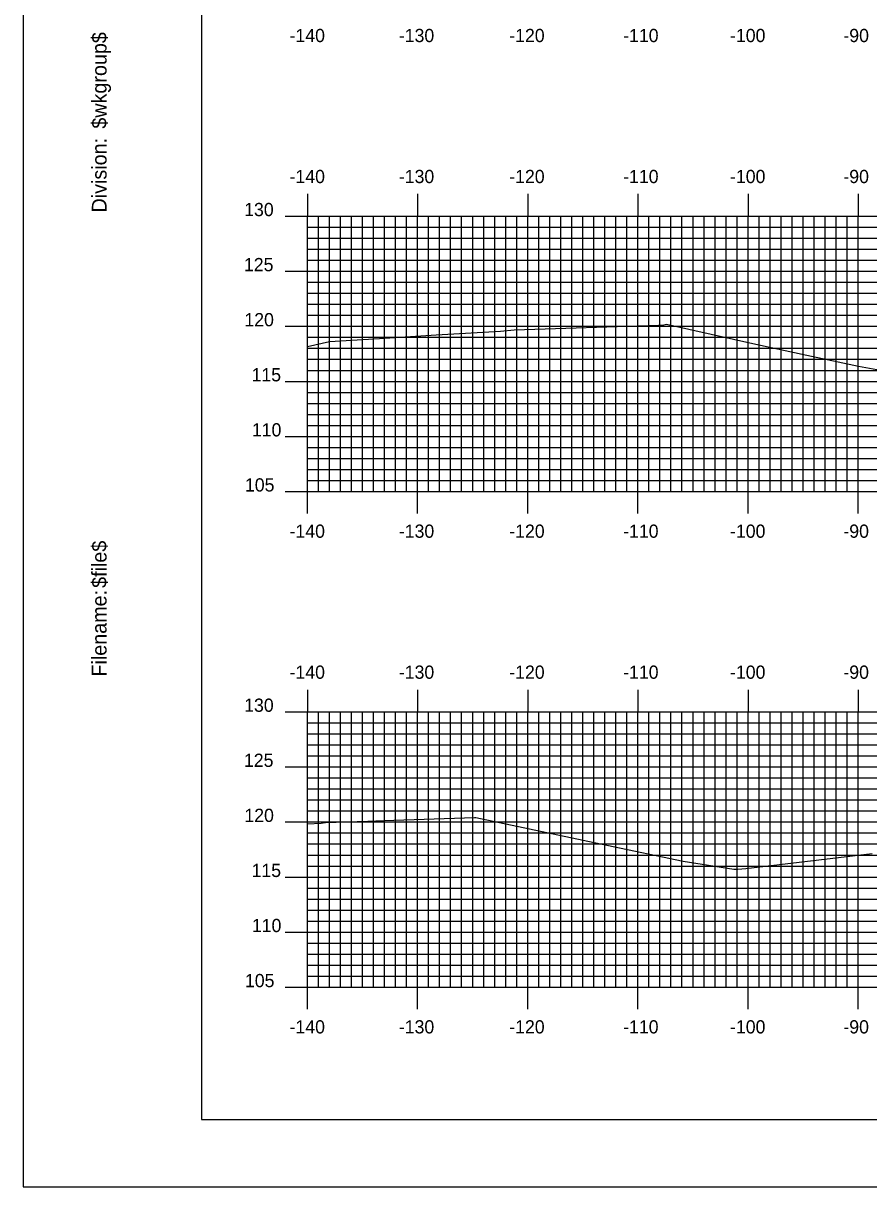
# Model space of a CAD drawing. Extents: x 1685979 to 1686323, y 461260 to 461480.
# Drawn here: x 1685979.5 to 1686056.2, y 461260 to 461365.6 of the extents above; entities that cross this region are included whole.
import ezdxf

# ---------------------------------------------------------------- set-up
doc = ezdxf.new("R2010")
doc.units = 0
for name, color, linetype in [('BORDER', 7, 'Continuous'), ('H_V ANNOTATION', 7, 'Continuous'), ('M_Roadway_Centerline', 7, 'Continuous'), ('MAJOR', 7, 'Continuous'), ('MINOR', 7, 'Continuous'), ('PLOT BOUNDARY', 7, 'Continuous'), ('S_Roadway_Centerline', 7, 'Continuous')]:
    doc.layers.add(name, color=color, linetype=linetype)

msp = doc.modelspace()

# ---------------------------------------------------------------- linework, layer by layer
at = {"layer": 'BORDER'}
msp.add_lwpolyline([(1685995.66, 461266.07), (1686315.66, 461266.07), (1686315.66, 461476.07), (1685995.66, 461476.07)], close=True, dxfattribs=at)
at = {"layer": 'MAJOR'}
for p, q in [((1686005.26, 461350.08), (1686005.26, 461348.07)), ((1686015.26, 461350.08), (1686015.26, 461348.07)), ((1686025.26, 461350.08), (1686025.26, 461348.07)), ((1686035.26, 461350.08), (1686035.26, 461348.07)), ((1686045.26, 461350.08), (1686045.26, 461348.07)), ((1686055.26, 461350.08), (1686055.26, 461348.07)), ((1686003.25, 461348.07), (1686005.26, 461348.07)), ((1686005.26, 461348.07), (1686285.26, 461348.07)), ((1686005.26, 461323.07), (1686005.26, 461348.07)), ((1686005.26, 461323.07), (1686005.26, 461348.07)), ((1686005.26, 461348.07), (1686285.26, 461348.07)), ((1686015.26, 461323.07), (1686015.26, 461348.07)), ((1686025.26, 461323.07), (1686025.26, 461348.07)), ((1686035.26, 461323.07), (1686035.26, 461348.07)), ((1686045.26, 461323.07), (1686045.26, 461348.07)), ((1686055.26, 461323.07), (1686055.26, 461348.07)), ((1686003.25, 461343.07), (1686005.26, 461343.07)), ((1686005.26, 461343.07), (1686285.26, 461343.07)), ((1686003.25, 461338.07), (1686005.26, 461338.07)), ((1686005.26, 461338.07), (1686285.26, 461338.07)), ((1686003.25, 461333.07), (1686005.26, 461333.07)), ((1686005.26, 461333.07), (1686285.26, 461333.07)), ((1686003.25, 461328.07), (1686005.26, 461328.07)), ((1686005.26, 461328.07), (1686285.26, 461328.07)), ((1686003.25, 461323.07), (1686005.26, 461323.07)), ((1686005.26, 461323.07), (1686285.26, 461323.07)), ((1686005.26, 461323.07), (1686285.26, 461323.07)), ((1686005.26, 461321.07), (1686005.26, 461323.07)), ((1686015.26, 461321.07), (1686015.26, 461323.07)), ((1686025.26, 461321.07), (1686025.26, 461323.07)), ((1686035.26, 461321.07), (1686035.26, 461323.07)), ((1686045.26, 461321.07), (1686045.26, 461323.07)), ((1686055.26, 461321.07), (1686055.26, 461323.07)), ((1686005.26, 461305.08), (1686005.26, 461303.07)), ((1686015.26, 461305.08), (1686015.26, 461303.07)), ((1686025.26, 461305.08), (1686025.26, 461303.07)), ((1686035.26, 461305.08), (1686035.26, 461303.07)), ((1686045.26, 461305.08), (1686045.26, 461303.07)), ((1686055.26, 461305.08), (1686055.26, 461303.07)), ((1686003.25, 461303.07), (1686005.26, 461303.07)), ((1686005.26, 461303.07), (1686285.26, 461303.07)), ((1686005.26, 461278.07), (1686005.26, 461303.07)), ((1686005.26, 461278.07), (1686005.26, 461303.07)), ((1686005.26, 461303.07), (1686285.26, 461303.07)), ((1686015.26, 461278.07), (1686015.26, 461303.07)), ((1686025.26, 461278.07), (1686025.26, 461303.07)), ((1686035.26, 461278.07), (1686035.26, 461303.07)), ((1686045.26, 461278.07), (1686045.26, 461303.07)), ((1686055.26, 461278.07), (1686055.26, 461303.07)), ((1686003.25, 461298.07), (1686005.26, 461298.07)), ((1686005.26, 461298.07), (1686285.26, 461298.07)), ((1686003.25, 461293.07), (1686005.26, 461293.07)), ((1686005.26, 461293.07), (1686285.26, 461293.07)), ((1686003.25, 461288.07), (1686005.26, 461288.07)), ((1686005.26, 461288.07), (1686285.26, 461288.07)), ((1686003.25, 461283.07), (1686005.26, 461283.07)), ((1686005.26, 461283.07), (1686285.26, 461283.07)), ((1686003.25, 461278.07), (1686005.26, 461278.07)), ((1686005.26, 461278.07), (1686285.26, 461278.07)), ((1686005.26, 461278.07), (1686285.26, 461278.07)), ((1686005.26, 461276.07), (1686005.26, 461278.07)), ((1686015.26, 461276.07), (1686015.26, 461278.07)), ((1686025.26, 461276.07), (1686025.26, 461278.07)), ((1686035.26, 461276.07), (1686035.26, 461278.07)), ((1686045.26, 461276.07), (1686045.26, 461278.07)), ((1686055.26, 461276.07), (1686055.26, 461278.07))]:
    msp.add_line(p, q, dxfattribs=at)
at = {"layer": 'MINOR'}
for p, q in [((1686006.26, 461323.07), (1686006.26, 461348.07)), ((1686007.26, 461323.07), (1686007.26, 461348.07)), ((1686008.26, 461323.07), (1686008.26, 461348.07)), ((1686009.26, 461323.07), (1686009.26, 461348.07)), ((1686010.26, 461323.07), (1686010.26, 461348.07)), ((1686011.26, 461323.07), (1686011.26, 461348.07)), ((1686012.26, 461323.07), (1686012.26, 461348.07)), ((1686013.26, 461323.07), (1686013.26, 461348.07)), ((1686014.26, 461323.07), (1686014.26, 461348.07)), ((1686016.26, 461323.07), (1686016.26, 461348.07)), ((1686017.26, 461323.07), (1686017.26, 461348.07)), ((1686018.26, 461323.07), (1686018.26, 461348.07)), ((1686019.26, 461323.07), (1686019.26, 461348.07)), ((1686020.26, 461323.07), (1686020.26, 461348.07)), ((1686021.26, 461323.07), (1686021.26, 461348.07)), ((1686022.26, 461323.07), (1686022.26, 461348.07)), ((1686023.26, 461323.07), (1686023.26, 461348.07)), ((1686024.26, 461323.07), (1686024.26, 461348.07)), ((1686026.26, 461323.07), (1686026.26, 461348.07)), ((1686027.26, 461323.07), (1686027.26, 461348.07)), ((1686028.26, 461323.07), (1686028.26, 461348.07)), ((1686029.26, 461323.07), (1686029.26, 461348.07)), ((1686030.26, 461323.07), (1686030.26, 461348.07)), ((1686031.26, 461323.07), (1686031.26, 461348.07)), ((1686032.26, 461323.07), (1686032.26, 461348.07)), ((1686033.26, 461323.07), (1686033.26, 461348.07)), ((1686034.26, 461323.07), (1686034.26, 461348.07)), ((1686036.26, 461323.07), (1686036.26, 461348.07)), ((1686037.26, 461323.07), (1686037.26, 461348.07)), ((1686038.26, 461323.07), (1686038.26, 461348.07)), ((1686039.26, 461323.07), (1686039.26, 461348.07)), ((1686040.26, 461323.07), (1686040.26, 461348.07)), ((1686041.26, 461323.07), (1686041.26, 461348.07)), ((1686042.26, 461323.07), (1686042.26, 461348.07)), ((1686043.26, 461323.07), (1686043.26, 461348.07)), ((1686044.26, 461323.07), (1686044.26, 461348.07)), ((1686046.26, 461323.07), (1686046.26, 461348.07)), ((1686047.26, 461323.07), (1686047.26, 461348.07)), ((1686048.26, 461323.07), (1686048.26, 461348.07)), ((1686049.26, 461323.07), (1686049.26, 461348.07)), ((1686050.26, 461323.07), (1686050.26, 461348.07)), ((1686051.26, 461323.07), (1686051.26, 461348.07)), ((1686052.26, 461323.07), (1686052.26, 461348.07)), ((1686053.26, 461323.07), (1686053.26, 461348.07)), ((1686054.26, 461323.07), (1686054.26, 461348.07)), ((1686005.26, 461347.07), (1686285.26, 461347.07)), ((1686005.26, 461347.07), (1686007.26, 461347.07)), ((1686005.26, 461346.07), (1686285.26, 461346.07)), ((1686005.26, 461346.07), (1686007.26, 461346.07)), ((1686005.26, 461345.07), (1686285.26, 461345.07)), ((1686005.26, 461345.07), (1686007.26, 461345.07)), ((1686005.26, 461344.07), (1686285.26, 461344.07)), ((1686005.26, 461344.07), (1686007.26, 461344.07)), ((1686005.26, 461342.07), (1686285.26, 461342.07)), ((1686005.26, 461342.07), (1686007.26, 461342.07)), ((1686005.26, 461341.07), (1686285.26, 461341.07)), ((1686005.26, 461341.07), (1686007.26, 461341.07)), ((1686005.26, 461340.07), (1686285.26, 461340.07)), ((1686005.26, 461340.07), (1686007.26, 461340.07)), ((1686005.26, 461339.07), (1686285.26, 461339.07)), ((1686005.26, 461339.07), (1686007.26, 461339.07)), ((1686005.26, 461337.07), (1686285.26, 461337.07)), ((1686005.26, 461337.07), (1686007.26, 461337.07)), ((1686005.26, 461336.07), (1686285.26, 461336.07)), ((1686005.26, 461336.07), (1686007.26, 461336.07)), ((1686005.26, 461335.07), (1686285.26, 461335.07)), ((1686005.26, 461335.07), (1686007.26, 461335.07)), ((1686005.26, 461334.07), (1686285.26, 461334.07)), ((1686005.26, 461334.07), (1686007.26, 461334.07)), ((1686005.26, 461332.07), (1686285.26, 461332.07)), ((1686005.26, 461332.07), (1686007.26, 461332.07)), ((1686005.26, 461331.07), (1686285.26, 461331.07)), ((1686005.26, 461331.07), (1686007.26, 461331.07)), ((1686005.26, 461330.07), (1686285.26, 461330.07)), ((1686005.26, 461330.07), (1686007.26, 461330.07)), ((1686005.26, 461329.07), (1686285.26, 461329.07)), ((1686005.26, 461329.07), (1686007.26, 461329.07)), ((1686005.26, 461327.07), (1686285.26, 461327.07)), ((1686005.26, 461327.07), (1686007.26, 461327.07)), ((1686005.26, 461326.07), (1686285.26, 461326.07)), ((1686005.26, 461326.07), (1686007.26, 461326.07)), ((1686005.26, 461325.07), (1686285.26, 461325.07)), ((1686005.26, 461325.07), (1686007.26, 461325.07)), ((1686005.26, 461324.07), (1686285.26, 461324.07)), ((1686005.26, 461324.07), (1686007.26, 461324.07)), ((1686006.26, 461278.07), (1686006.26, 461303.07)), ((1686007.26, 461278.07), (1686007.26, 461303.07)), ((1686008.26, 461278.07), (1686008.26, 461303.07)), ((1686009.26, 461278.07), (1686009.26, 461303.07)), ((1686010.26, 461278.07), (1686010.26, 461303.07)), ((1686011.26, 461278.07), (1686011.26, 461303.07)), ((1686012.26, 461278.07), (1686012.26, 461303.07)), ((1686013.26, 461278.07), (1686013.26, 461303.07)), ((1686014.26, 461278.07), (1686014.26, 461303.07)), ((1686016.26, 461278.07), (1686016.26, 461303.07)), ((1686017.26, 461278.07), (1686017.26, 461303.07)), ((1686018.26, 461278.07), (1686018.26, 461303.07)), ((1686019.26, 461278.07), (1686019.26, 461303.07)), ((1686020.26, 461278.07), (1686020.26, 461303.07)), ((1686021.26, 461278.07), (1686021.26, 461303.07)), ((1686022.26, 461278.07), (1686022.26, 461303.07)), ((1686023.26, 461278.07), (1686023.26, 461303.07)), ((1686024.26, 461278.07), (1686024.26, 461303.07)), ((1686026.26, 461278.07), (1686026.26, 461303.07)), ((1686027.26, 461278.07), (1686027.26, 461303.07)), ((1686028.26, 461278.07), (1686028.26, 461303.07)), ((1686029.26, 461278.07), (1686029.26, 461303.07)), ((1686030.26, 461278.07), (1686030.26, 461303.07)), ((1686031.26, 461278.07), (1686031.26, 461303.07)), ((1686032.26, 461278.07), (1686032.26, 461303.07)), ((1686033.26, 461278.07), (1686033.26, 461303.07)), ((1686034.26, 461278.07), (1686034.26, 461303.07)), ((1686036.26, 461278.07), (1686036.26, 461303.07)), ((1686037.26, 461278.07), (1686037.26, 461303.07)), ((1686038.26, 461278.07), (1686038.26, 461303.07)), ((1686039.26, 461278.07), (1686039.26, 461303.07)), ((1686040.26, 461278.07), (1686040.26, 461303.07)), ((1686041.26, 461278.07), (1686041.26, 461303.07)), ((1686042.26, 461278.07), (1686042.26, 461303.07)), ((1686043.26, 461278.07), (1686043.26, 461303.07)), ((1686044.26, 461278.07), (1686044.26, 461303.07)), ((1686046.26, 461278.07), (1686046.26, 461303.07)), ((1686047.26, 461278.07), (1686047.26, 461303.07)), ((1686048.26, 461278.07), (1686048.26, 461303.07)), ((1686049.26, 461278.07), (1686049.26, 461303.07)), ((1686050.26, 461278.07), (1686050.26, 461303.07)), ((1686051.26, 461278.07), (1686051.26, 461303.07)), ((1686052.26, 461278.07), (1686052.26, 461303.07)), ((1686053.26, 461278.07), (1686053.26, 461303.07)), ((1686054.26, 461278.07), (1686054.26, 461303.07)), ((1686005.26, 461302.07), (1686285.26, 461302.07)), ((1686005.26, 461302.07), (1686007.26, 461302.07)), ((1686005.26, 461301.07), (1686285.26, 461301.07)), ((1686005.26, 461301.07), (1686007.26, 461301.07)), ((1686005.26, 461300.07), (1686285.26, 461300.07)), ((1686005.26, 461300.07), (1686007.26, 461300.07)), ((1686005.26, 461299.07), (1686285.26, 461299.07)), ((1686005.26, 461299.07), (1686007.26, 461299.07)), ((1686005.26, 461297.07), (1686285.26, 461297.07)), ((1686005.26, 461297.07), (1686007.26, 461297.07)), ((1686005.26, 461296.07), (1686285.26, 461296.07)), ((1686005.26, 461296.07), (1686007.26, 461296.07)), ((1686005.26, 461295.07), (1686285.26, 461295.07)), ((1686005.26, 461295.07), (1686007.26, 461295.07)), ((1686005.26, 461294.07), (1686285.26, 461294.07)), ((1686005.26, 461294.07), (1686007.26, 461294.07)), ((1686005.26, 461292.07), (1686285.26, 461292.07)), ((1686005.26, 461292.07), (1686007.26, 461292.07)), ((1686005.26, 461291.07), (1686285.26, 461291.07)), ((1686005.26, 461291.07), (1686007.26, 461291.07)), ((1686005.26, 461290.07), (1686285.26, 461290.07)), ((1686005.26, 461290.07), (1686007.26, 461290.07)), ((1686005.26, 461289.07), (1686285.26, 461289.07)), ((1686005.26, 461289.07), (1686007.26, 461289.07)), ((1686005.26, 461287.07), (1686285.26, 461287.07)), ((1686005.26, 461287.07), (1686007.26, 461287.07)), ((1686005.26, 461286.07), (1686285.26, 461286.07)), ((1686005.26, 461286.07), (1686007.26, 461286.07)), ((1686005.26, 461285.07), (1686285.26, 461285.07)), ((1686005.26, 461285.07), (1686007.26, 461285.07)), ((1686005.26, 461284.07), (1686285.26, 461284.07)), ((1686005.26, 461284.07), (1686007.26, 461284.07)), ((1686005.26, 461282.07), (1686285.26, 461282.07)), ((1686005.26, 461282.07), (1686007.26, 461282.07)), ((1686005.26, 461281.07), (1686285.26, 461281.07)), ((1686005.26, 461281.07), (1686007.26, 461281.07)), ((1686005.26, 461280.07), (1686285.26, 461280.07)), ((1686005.26, 461280.07), (1686007.26, 461280.07)), ((1686005.26, 461279.07), (1686285.26, 461279.07)), ((1686005.26, 461279.07), (1686007.26, 461279.07))]:
    msp.add_line(p, q, dxfattribs=at)
at = {"layer": 'PLOT BOUNDARY'}
msp.add_lwpolyline([(1685979.47, 461259.95), (1686319.47, 461259.95), (1686319.47, 461479.95), (1685979.47, 461479.95)], close=True, dxfattribs=at)
at = {"layer": 'S_Roadway_Centerline'}
for points in [[(1686005.26, 461336.24), (1686007.27, 461336.69), (1686011.79, 461336.96), (1686016.94, 461337.28), (1686022.78, 461337.64), (1686024.04, 461337.75), (1686037.12, 461338.17), (1686037.6, 461338.19), (1686037.84, 461338.25), (1686045.96, 461336.46), (1686050.58, 461335.44), (1686055.28, 461334.45), (1686057.29, 461334.09)], [(1686005.26, 461292.89), (1686006.51, 461292.96), (1686006.9, 461293.01), (1686010.74, 461293.13), (1686012.19, 461293.19), (1686020.44, 461293.47), (1686020.55, 461293.47), (1686032.43, 461290.95), (1686039.38, 461289.51), (1686043.97, 461288.79), (1686044.32, 461288.79), (1686045.06, 461288.85), (1686056.53, 461290.21)]]:
    msp.add_lwpolyline(points, dxfattribs=at)

# ---------------------------------------------------------------- texts
at = {"layer": 'BORDER'}
for s, p in [('$wkgroup$', (1685987.03, 461356.01)), ('Division:', (1685987.03, 461348.4)), ('$file$', (1685987.03, 461314.32)), ('Filename:', (1685987.03, 461306.27))]:
    msp.add_text(s, height=1.339, rotation=90, dxfattribs=at).set_placement(p)
at = {"layer": 'H_V ANNOTATION'}
for s, p in [('-140', (1686003.64, 461363.87)), ('-130', (1686013.56, 461363.87)), ('-120', (1686023.58, 461363.87)), ('-110', (1686033.92, 461363.87)), ('-100', (1686043.62, 461363.87)), ('-90', (1686053.91, 461363.87)), ('-140', (1686003.64, 461351.07)), ('-130', (1686013.56, 461351.07)), ('-120', (1686023.58, 461351.07)), ('-110', (1686033.92, 461351.07)), ('-100', (1686043.62, 461351.07)), ('-90', (1686053.91, 461351.07)), ('130', (1685999.52, 461348.07)), ('125', (1685999.5, 461343.07)), ('120', (1685999.54, 461338.07)), ('115', (1686000.19, 461333.07)), ('110', (1686000.22, 461328.07)), ('105', (1685999.59, 461323.07)), ('-140', (1686003.64, 461318.87)), ('-130', (1686013.56, 461318.87)), ('-120', (1686023.58, 461318.87)), ('-110', (1686033.92, 461318.87)), ('-100', (1686043.62, 461318.87)), ('-90', (1686053.91, 461318.87)), ('-140', (1686003.64, 461306.07)), ('-130', (1686013.56, 461306.07)), ('-120', (1686023.58, 461306.07)), ('-110', (1686033.92, 461306.07)), ('-100', (1686043.62, 461306.07)), ('-90', (1686053.91, 461306.07)), ('130', (1685999.52, 461303.07)), ('125', (1685999.5, 461298.07)), ('120', (1685999.54, 461293.07)), ('115', (1686000.19, 461288.07)), ('110', (1686000.22, 461283.07)), ('105', (1685999.59, 461278.07)), ('-140', (1686003.64, 461273.87)), ('-130', (1686013.56, 461273.87)), ('-120', (1686023.58, 461273.87)), ('-110', (1686033.92, 461273.87)), ('-100', (1686043.62, 461273.87)), ('-90', (1686053.91, 461273.87))]:
    msp.add_text(s, height=1.2, dxfattribs=at).set_placement(p)
at = {"layer": 'M_Roadway_Centerline'}
for s, p in [('C', (1686024.03, 461337.75)), ('L', (1686024.04, 461337.74)), ('C', (1686006.89, 461293.01)), ('L', (1686006.9, 461293))]:
    msp.add_text(s, height=0.0146, dxfattribs=at).set_placement(p)
at = {"layer": 'MAJOR'}
for p in [(1686005.25, 461323.07), (1686005.25, 461278.07)]:
    msp.add_text('-', height=0.012, dxfattribs=at).set_placement(p)

doc.saveas('drawing.dxf')
